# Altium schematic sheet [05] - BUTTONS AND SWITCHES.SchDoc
size A4; DocumentNumber: 5; SheetNumber: 5; SheetTotal: 5
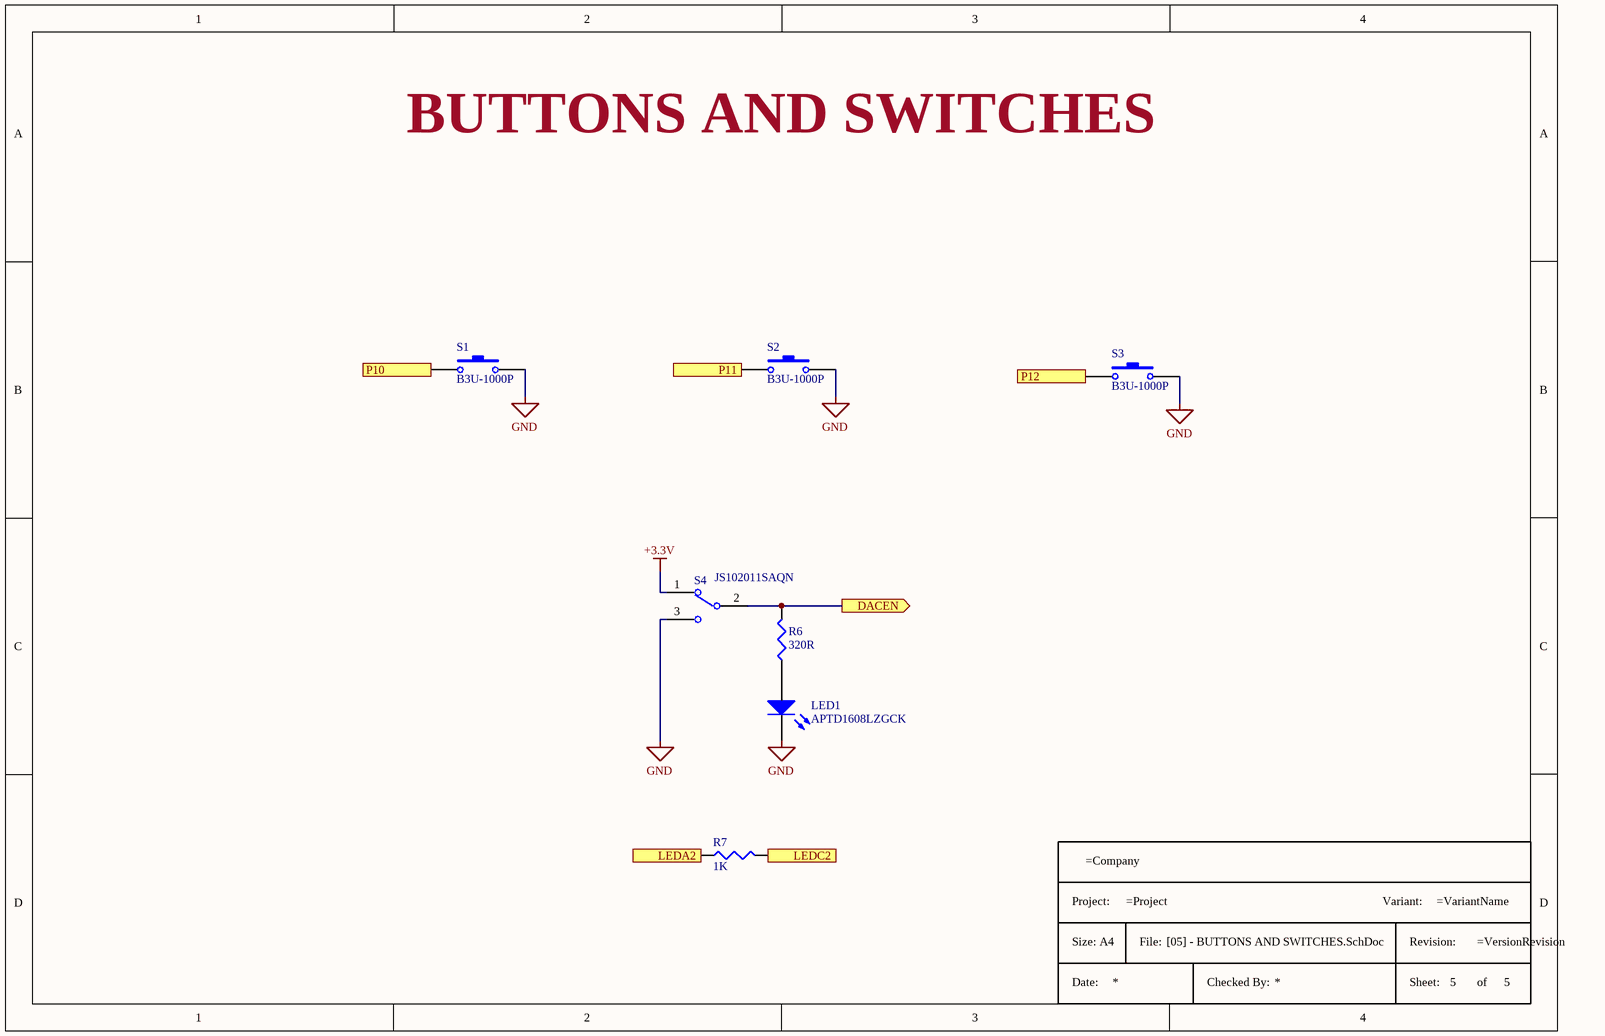
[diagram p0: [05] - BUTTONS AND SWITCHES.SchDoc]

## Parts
*  Title Block A4  (value not drawn)  (graphical)
LED1  APTD1608LZGCK  [RESC0603X55N]
R6  320R  [R0603]
R7  1K  [R0603]
S1  B3U-1000P  [SW_B3U-1000P]
S2  B3U-1000P  [SW_B3U-1000P]
S3  B3U-1000P  [SW_B3U-1000P]
S4  JS102011SAQN  [SW_JS102011SAQN]

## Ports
DACEN (out), LEDA2 (in), LEDC2 (in), P10 (out), P11 (out), P12 (out)

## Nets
+3.3V: S4.1
GND: LED1.1(K) S1.2 S2.2 S3.2 S4.3
DACEN: R6.2 S4.2 ; port DACEN
LEDA2: R7.1 ; port LEDA2
LEDC2: R7.2 ; port LEDC2
P10: S1.1 ; port P10
P11: S2.1 ; port P11
P12: S3.1 ; port P12
NetLED1_2: LED1.2(A) R6.1

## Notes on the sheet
- BUTTONS AND SWITCHES

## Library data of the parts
LED1 = APTD1608LZGCK: LED GREEN CLEAR 0603 SMD; Manufacturer: Kingbright; Lens Color: Colorless; Luminous Intensity: 90mcd; Test Current: 2mA; Viewing Angle: 60°; Dominant Wavelength: 525nm; Forward Voltage: 2.65V
R6 = RT0603DRE07320RL: High Precision-High Stability Chip Resistor Thin Film 0603 320Ohm 0.5% Paper T/R; Manufacturer: Yageo; Max Power Dissipation: 100mW; Temperature Coefficient: 50ppm/°C
R7 = ESR03EZPF1001: ROHM - ESR03EZPF1001 - SMD Chip Resistor, Anti-Surge, 0603 [1608 Metric], 1 kohm, ESR Series, 150 V, Thick Film, 250 mW; Temperature Coefficient: 100ppm/°C; Max Power Dissipation: 250mW; Resistance: 1kR; Tolerance: 1%
S1-S3 = B3U-1000P: SWITCH TACTILE SPST-NO 0.05A 12V; Manufacturer: Omron; Mechanical Life: 200000Cycles; Operating Force: 1.5N; Throw Configuration: SPST; Current Rating: 50mA; Contact Resistance: 100mR; Illumination Type: Non-Illuminated,Illuminated; Switch Travel: 0.15mm; Switch Function: Off-Mom; Actuator Type: Standard; Actuator Length: 0.4mm; Ratings: Dust Proof,IP40
S4 = JS102011SAQN: Slide Switch, JS Series, SPDT, Right Angle, SMD, 100 mA ;RoHS Compliant: Yes; Manufacturer: ITT C&K; Actuator Material: Nylon,Polyamide; Max Voltage Rating (DC): 6V; Max Current Rating: 300mA; Contact Resistance: 70mR; Electrical Life: 5000Cycles; Illumination Type: Non-Illuminated; Switch Travel: 2mm; Switch Function: On-On; Actuator Type: Standard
